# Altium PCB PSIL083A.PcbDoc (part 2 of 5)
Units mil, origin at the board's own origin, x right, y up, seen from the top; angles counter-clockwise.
Board outline 8750 x 2700 mil, 4 copper layers (Top Layer, Signal Layer 1, Signal Layer 2, Bottom Layer), stack 61.2 mil thick; 463 components, 395 nets, 2267 pads, 745 vias.
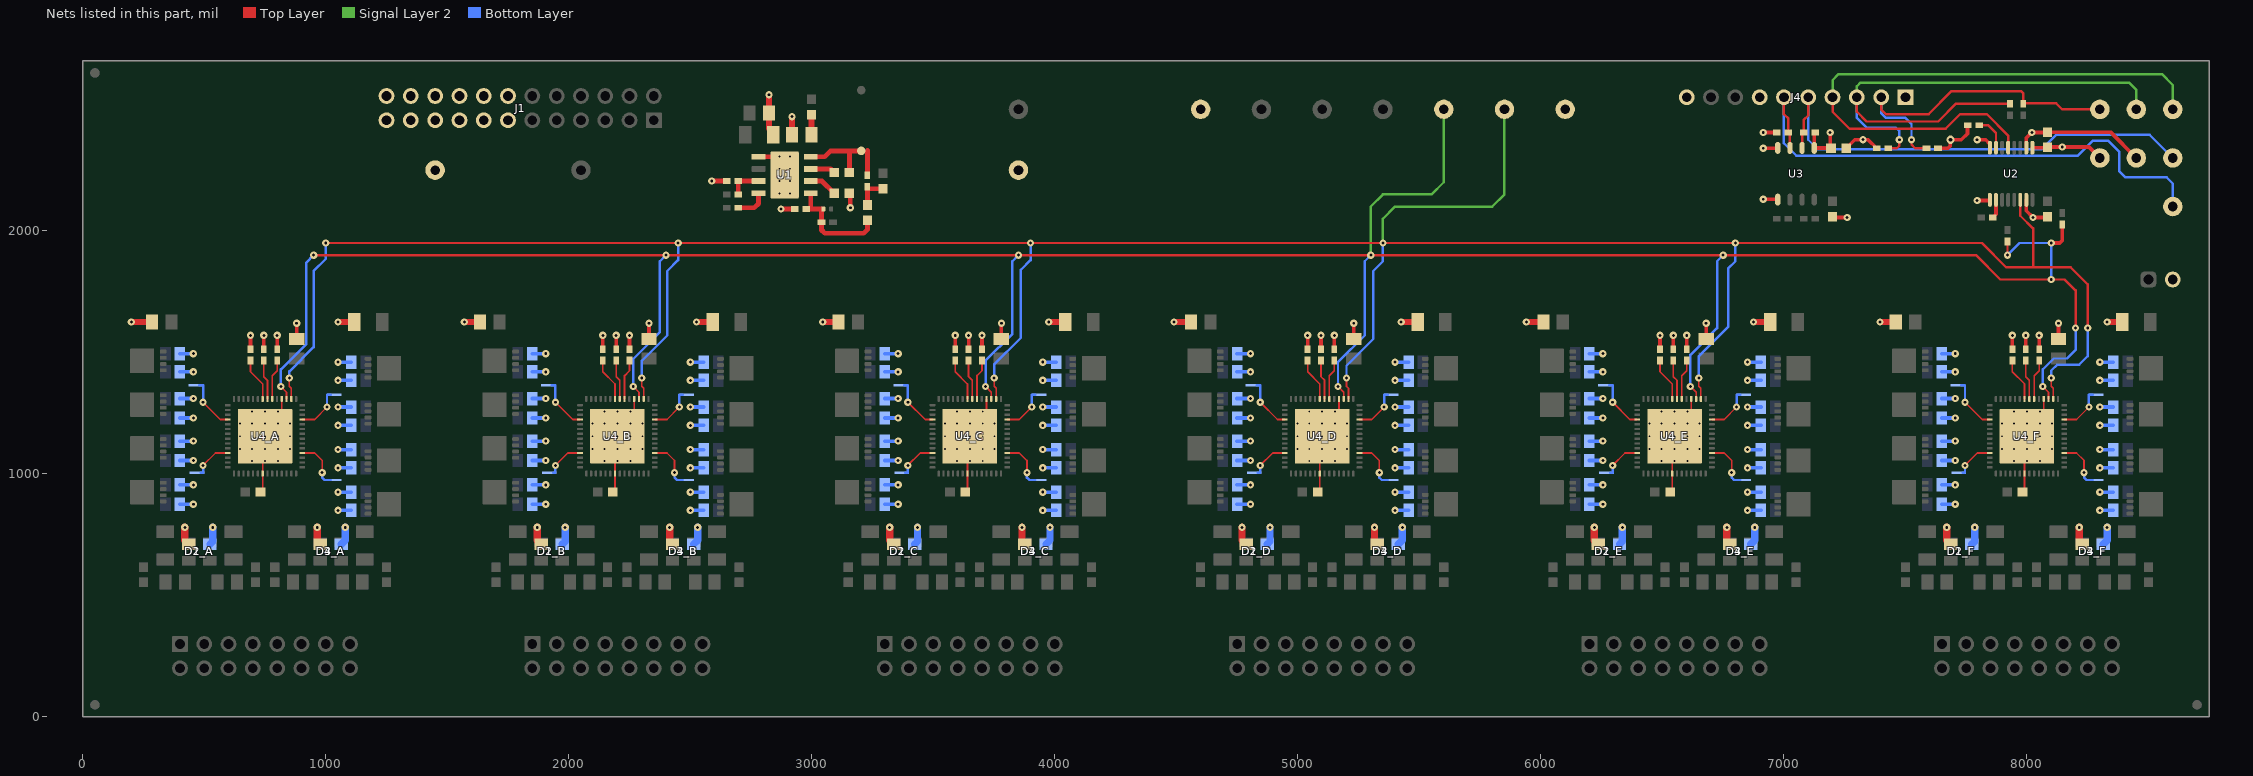
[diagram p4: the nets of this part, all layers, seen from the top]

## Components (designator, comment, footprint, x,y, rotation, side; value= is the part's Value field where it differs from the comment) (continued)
ZZ3 "These assemblies must be clean and free from flux and all contaminants. Use of no clean flux is not acceptable." AssemblyNote 175,4190 r0 top
ZZ4 "These assemblies must comply with workmanship standards IPC-A-610 Class 2, unless otherwise specified." AssemblyNote 170,4015 r0 top
ZZ5 "DO NOT TRIM CONNECTOR PINS on J5" AssemblyNote 170,3815 r0 top

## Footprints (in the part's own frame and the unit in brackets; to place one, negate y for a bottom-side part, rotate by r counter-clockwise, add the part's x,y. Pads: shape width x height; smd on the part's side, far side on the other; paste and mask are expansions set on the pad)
0402 [mm] "0402 from SM-752 data"
  rect 0.8x0.6 smd: 1(-0.6,0) 2(0.6,0)
  silkscreen extent -1.22,-0.52 1.22,0.52, body extent -0.55,-0.3 0.55,0.3, height 0.6
0603 [mm] "0603 from SM-752 data"
  rect 1x0.95 smd: 1(-0.8,0) 2(0.8,0)
  silkscreen extent -1.52,-0.69 1.52,0.69, body extent -0.87,-0.47 0.87,0.47, height 1
0805_HV [mil] "0805 with 30mil clearance between pads"
  rect 50x63 smd: 1(-40,0) 2(40,0)
  silkscreen extent -74,-40 74,40, body extent -43,-29 43,29, height 57
0805L [mm] "0805 from SM-752 data"
  rect 1.1x1.4 smd: 1(-0.75,0) 2(0.75,0)
  body extent -1.1,-0.72 1.1,0.72, height 1.45
1206 [mm] "1206 from SM-752 data"
  rect 1.3x1.85 smd: 1(-1.45,0) 2(1.45,0)
  silkscreen extent -2.4,-1.21 2.4,1.21, body extent -1.7,-0.9 1.7,0.9, height 1.35
AssemblyNote [mil] "Assembly Note"
AssemblyNoteLabel [mil] "Assembly Note for PCB Labels"
CE_Mark_5mm [mil] "Minimum text height for CE Mark"
  silkscreen extent -138,-98 138,98
D0008B_L [mm] "SOIC, 8-Leads, Body 4.9x3.9mm, Pitch 1.27mm, IPC High Density"
  oval 1.25x0.55 smd: 1(-2.7,1.905) 2(-2.7,0.635) 3(-2.7,-0.635) 4(-2.7,-1.905) 5(2.7,-1.905) 6(2.7,-0.635) 7(2.7,0.635) 8(2.7,1.905)
  silkscreen extent -3.1,-2.5 0.9,2.5, body extent -3,-2.45 3,2.45, height 1.63
DBQ0016A_N [mm] "SOP, 16-Leads, Body 4.9x3.9mm, Pitch 0.635mm, IPC Medium Density"
  oval 1.45x0.4 smd: 1(-2.725,2.222) 2(-2.725,1.587) 3(-2.725,0.952) 4(-2.725,0.317) 5(-2.725,-0.318) 6(-2.725,-0.953) 7(-2.725,-1.588) 8(-2.725,-2.223) 9(2.725,-2.222) 10(2.725,-1.587) 11(2.725,-0.952) 12(2.725,-0.317) 13(2.725,0.318) 14(2.725,0.953) 15(2.725,1.588) 16(2.725,2.223)
  silkscreen extent -3.35,-2.5 1.1,2.68, body extent -3.01,-2.45 3.01,2.45, height 1.63
DDA0008B_N [mm] "SOIC, 8-Leads, Body 4.9x3.9mm, Pitch 1.27mm, Exposed Pad, IPC Medium Density"
  rrect17% 1.45x0.6 smd: 1(-2.725,1.905) 2(-2.725,0.635) 3(-2.725,-0.635) 4(-2.725,-1.905) 5(2.725,-1.905) 6(2.725,-0.635) 7(2.725,0.635) 8(2.725,1.905)
  rrect7% 2.95x4.9 smd paste-1.5 mask-1.5: 9(0,0)
  rrect4% 2.71x3.4 on Top Paste: 9(0,0)
  rrect4% 2.71x3.4 on Top Solder: 9(0,0)
  silkscreen extent -3.5,-2.5 1.1,2.5, body extent -3.01,-2.45 3.01,2.45, height 1.57
DNH0008A_NV [mm] "8 pin VSONP, 0.65 mm pitch"
  rrect50% 0.7x0.4 smd paste-0.05 mask-0.05: 1(-1.55,0.975) 2(-1.55,0.325) 3(-1.55,-0.325) 4(-1.55,-0.975) 5(1.55,-0.975) 6(1.55,-0.325) 7(1.55,0.325) 8(1.55,0.975)
  rrect14% 0.705x1.125 on Top Paste: 9(-0.208,0.662) 9(-0.208,-0.663) 9(0.697,0.662) 9(0.697,-0.663)
  rrect6% 1.775x2.45 on Top Solder: 9(0.327,0)
  rrect4% 2.51x2.55 smd paste-1.5 mask-1.5: 9(0.645,0)
  rect 0.5x0.3 on Top Solder: 9(1.175,0.975) 9(1.175,-0.325) 9(1.175,0.325) 9(1.175,-0.975)
  silkscreen extent -1.62,-1.7 1.62,1.7, body extent -1.65,-1.65 1.65,1.66, height 0.91
FCC_disclaimer [mil]
Fiducial10-20 [mm]
  round 1 smd mask+0.5: 1(0,0)
  Top Layer keep-out circle w1.178: c0,0 r0.5
FP-GCM1555C1H121FA16D_0402-MFG [mm]
  rrect25% 0.4x0.5 smd paste+0 mask+0: 1(-0.4,0) 2(0.4,0)
  body extent -0.7,-0.38 0.7,0.38, height 0.25
Keystone5000 [mil] "For Keystone 500x miniature loop terminals"
  round 80 hole 40: 1(0,0)
  silkscreen extent -52,-52 52,52, body extent -49,-49 49,49, height 182
Keystone5001 [mil] "For Keystone 500x miniature loop terminals"
  round 80 hole 40: 1(0,0)
  silkscreen extent -52,-52 52,52, body extent -49,-49 49,49, height 182
Keystone5002 [mil] "For Keystone 500x miniature loop terminals"
  round 80 hole 40: 1(0,0)
  silkscreen extent -52,-52 52,52, body extent -49,-49 49,49, height 182
Keystone5003 [mil] "For Keystone 500x miniature loop terminals"
  round 80 hole 40: 1(0,0)
  silkscreen extent -52,-52 52,52, body extent -49,-49 49,49, height 182
Label_650x200 [mil] "Thermal Transfer Label"
  round 1 on Mech13: 0(0,0)
  silkscreen extent -325,-100 325,100, body extent -325,-100 325,100, height 1
Net-Tie_10milWide_30milLong [mil] "10mil net tie, no solder mask opening, no solder paste"
  rect 30x10 smd paste-5 mask-5: 1(-15,0) 2(15,0)
RTQ0056E [mm] "QFN, 56-Leads, Body 8x8mm, Pitch 0.5mm, Thermal Pad 5.7x5.7mm, TI Recommended"
  rrect42% 0.6x0.24 smd: 1(-3.9,3.25) 2(-3.9,2.75) 3(-3.9,2.25) 4(-3.9,1.75) 5(-3.9,1.25) 6(-3.9,0.75) 7(-3.9,0.25) 8(-3.9,-0.25) 9(-3.9,-0.75) 10(-3.9,-1.25) 11(-3.9,-1.75) 12(-3.9,-2.25) 13(-3.9,-2.75) 14(-3.9,-3.25) 29(3.9,-3.25) 30(3.9,-2.75) 31(3.9,-2.25) 32(3.9,-1.75) 33(3.9,-1.25) 34(3.9,-0.75) 35(3.9,-0.25) 36(3.9,0.25) 37(3.9,0.75) 38(3.9,1.25) 39(3.9,1.75) 40(3.9,2.25) 41(3.9,2.75) 42(3.9,3.25)
  rrect42% 0.24x0.6 smd: 15(-3.25,-3.9) 16(-2.75,-3.9) 17(-2.25,-3.9) 18(-1.75,-3.9) 19(-1.25,-3.9) 20(-0.75,-3.9) 21(-0.25,-3.9) 22(0.25,-3.9) 23(0.75,-3.9) 24(1.25,-3.9) 25(1.75,-3.9) 26(2.25,-3.9) 27(2.75,-3.9) 28(3.25,-3.9) 43(3.25,3.9) 44(2.75,3.9) 45(2.25,3.9) 46(1.75,3.9) 47(1.25,3.9) 48(0.75,3.9) 49(0.25,3.9) 50(-0.25,3.9) 51(-0.75,3.9) 52(-1.25,3.9) 53(-1.75,3.9) 54(-2.25,3.9) 55(-2.75,3.9) 56(-3.25,3.9)
  rrect9% 1.15x1.15 on Top Paste: 57(-2.025,-2.025) 57(-2.025,-0.675) 57(-2.025,0.675) 57(-2.025,2.025) 57(-0.675,-2.025) 57(-0.675,-0.675) 57(-0.675,0.675) 57(-0.675,2.025) 57(0.675,-2.025) 57(0.675,-0.675) 57(0.675,0.675) 57(0.675,2.025) 57(2.025,-2.025) 57(2.025,-0.675) 57(2.025,0.675) 57(2.025,2.025)
  rrect2% 5.7x5.7 smd paste-3: 57(0,0)
  silkscreen extent -4.22,-4.23 4.22,4.23, body extent -4,-4 4,4, height 1
SOT-143-4 [mm] "Littelfuse"
  rect 1.4x1.2 smd: 1(-1.1,0.9)
  rect 1.4x1 smd: 2(-1.1,-0.8) 3(1.1,-0.8) 4(1.1,1.1)
  silkscreen extent -1.22,1.8 -1.02,2.01, body extent -0.7,-1.37 0.7,1.67, height 1.23
SPC02SYAN [mil] "SULLINS"
  round 1 on Mech3: 0(0,0)
  body extent -98,-47 99,47, height 366
TI_Stacked_Overlay_Small [mil]
  silkscreen extent -418,-98 418,98
TSW-102-07-G-S [mm] "Samtec 100mil, 1x2, 230 mil above insulator"
  rrect50% 1.65x1.65 hole 1.016: 1(-1.27,0)
  round 1.65 hole 1.016: 2(1.27,0)
  body extent -2.54,-1.27 2.54,1.27, height 8.38
TSW-108-07-G-D [mm] "Samtec 100mil, 2x8, 230 mil above insulator"
  rrect6% 1.65x1.65 hole 1.016: 1(-8.89,-1.27)
  round 1.65 hole 1.016: 2(-8.89,1.27) 3(-6.35,-1.27) 4(-6.35,1.27) 5(-3.81,-1.27) 6(-3.81,1.27) 7(-1.27,-1.27) 8(-1.27,1.27) 9(1.27,-1.27) 10(1.27,1.27) 11(3.81,-1.27) 12(3.81,1.27) 13(6.35,-1.27) 14(6.35,1.27) 15(8.89,-1.27) 16(8.89,1.27)
  silkscreen extent -11.18,-2.54 10.16,2.54, body extent -10.16,-2.54 10.16,2.54, height 8.38
TSW-110-07-G-S [mm] "Samtec 100mil, 1x10, 230 mil above insulator"
  rrect6% 1.65x1.65 hole 1.016: 1(-11.43,0)
  round 1.65 hole 1.016: 2(-8.89,0) 3(-6.35,0) 4(-3.81,0) 5(-1.27,0) 6(1.27,0) 7(3.81,0) 8(6.35,0) 9(8.89,0) 10(11.43,0)
  silkscreen extent -12.7,-1.27 12.7,1.65, body extent -12.7,-1.27 12.7,1.27, height 8.38
TSW-112-07-G-D [mm] "Samtec 100mil, 2x12, 230 mil above insulator"
  rrect6% 1.65x1.65 hole 1.016: 1(-13.97,-1.27)
  round 1.65 hole 1.016: 2(-13.97,1.27) 3(-11.43,-1.27) 4(-11.43,1.27) 5(-8.89,-1.27) 6(-8.89,1.27) 7(-6.35,-1.27) 8(-6.35,1.27) 9(-3.81,-1.27) 10(-3.81,1.27) 11(-1.27,-1.27) 12(-1.27,1.27) 13(1.27,-1.27) 14(1.27,1.27) 15(3.81,-1.27) 16(3.81,1.27) 17(6.35,-1.27) 18(6.35,1.27) 19(8.89,-1.27) 20(8.89,1.27) 21(11.43,-1.27) 22(11.43,1.27) 23(13.97,-1.27) 24(13.97,1.27)
  silkscreen extent -16.27,-2.54 15.24,2.54, body extent -15.24,-2.54 15.24,2.54, height 8.38
WE-TPC_6823 [mm] "Wurth"
  round 0.9 smd: 1(0,3.2) 2(0,-3.15)
  Top Layer region: 3.65,-1.05 2.5,-1.05 2.485,-1.055 1.743,-2.062 0.626,-2.626 -0.626,-2.626 -1.743,-2.062 -2.485,-1.055 -2.485,-1.055 -2.5,-1.05 -3.65,-1.05 -3.65,-3.65 3.65,-3.65
  Top Layer region: -3.65,1.05 -2.5,1.05 -2.485,1.055 -1.743,2.062 -0.626,2.626 0.626,2.626 1.743,2.062 2.485,1.055 2.485,1.055 2.5,1.05 3.65,1.05 3.65,3.65 -3.65,3.65
  body extent -3.5,-3.5 3.5,3.5, height 2.5
WEEE_Minimum [mil] "WEEElie bin"
  silkscreen extent -95,-172 99,104

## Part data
C1: library part CMP-0750039-1, "CAP, CERM, 0.01 µF, 50 V,+/- 10%, X7R, 0603", Cap_Case=0603, Manufacturer="Wurth Elektronik", TempCo=X7R, Tolerance_%=10%, Value2=50V, ValueDisplayed=0.01µF
C2 C5 C25 C27 C29 C31 C33: library part CMP-0750040-1, "CAP, CERM, 1 µF, 100 V,+/- 10%, X7R, AEC-Q200 Grade 1, 1206", Cap_Case=1206, Manufacturer=MuRata, TempCo=X7R, Tolerance_%=10%, Value2=100V, ValueDisplayed=1µF
C3 C4 C15_A C15_B C15_C C15_D C15_E C15_F C16_A C16_B C16_C C16_D C16_E C16_F C17_A C17_B C17_C C17_D C17_E C17_F C18_A C18_B C18_C C18_D C18_E C18_F C19_A C19_B C19_C C19_D C19_E C19_F C20_A C20_B C20_C C20_D C20_E C20_F C21_A C21_B C21_C C21_D C21_E C21_F C22_A C22_B C22_C C22_D C22_E C22_F C26 C28 C30 C32 C34: library part CMP-0007886-2, "CAP, CERM, 0.1 uF, 100 V, +/- 10%, X7R, 0805", Cap_Case=0805, Manufacturer=TDK, Supplier Part Number 1=445-1418-1-ND, TempCo=X7R, Tolerance_%=10%, Value1="0.020726 ohm", Value2=100V, ValueDisplayed=0.1uF
C6: library part CMP-0082012-1, "CAP, CERM, 1 µF, 16 V,+/- 20%, X7R, 0603", Cap_Case=0603, Manufacturer=Samsung, Supplier Part Number 1=1276-6524-1-ND, TempCo=X7R, Tolerance_%=20%, Value2=16V, ValueDisplayed=1µF
C7: library part CMP-0007691-2, "CAP, CERM, 10 uF, 10 V, +/- 10%, X7R, 0805", Cap_Case=0805, Manufacturer="Wurth Elektronik", Supplier Part Number 1=710-885012207026, TempCo=X7R, Tolerance_%=10%, Value1=Unknown, Value2=10V, ValueDisplayed=10uF
C8: library part CMP-0007210-4, "CAP, CERM, 3300 pF, 50 V, +/- 5%, C0G/NP0, 0603", Cap_Case=0603, Manufacturer=MuRata, Supplier Part Number 1=GRM1885C1H332JA01D-ND, TempCo=C0G/NP0, Tolerance_%=5%, Value1=Unknown, Value2=50V, ValueDisplayed=3300pF
C9 C10 C11 C12 C24: library part CMP-0006837-4, "CAP, CERM, 0.1 uF, 50 V, +/- 10%, X7R, 0603", Cap_Case=0603, Manufacturer="Wurth Elektronik", TempCo=X7R, Tolerance_%=10%, Value1=Unknown, Value2=50V, ValueDisplayed=0.1uF
C13_A C13_B C13_C C13_D C13_E C13_F: library part CMP-0007099-4, "CAP, CERM, 0.1 uF, 100 V, +/- 10%, X7S, AEC-Q200 Grade 1, 0603", Cap_Case=0603, Manufacturer=TDK, Supplier Part Number 1=445-6938-1-ND, TempCo=X7S, Tolerance_%=10%, Value1="0.04959 ohm", Value2=100V, ValueDisplayed=0.1uF
C14_A C14_B C14_C C14_D C14_E C14_F: library part CMP-0007724-2, "CAP, CERM, 0.1 uF, 16 V, +/- 10%, X7R, 0805", Cap_Case=0805, Manufacturer=Kemet, Supplier Part Number 1=399-1167-1-ND, TempCo=X7R, Tolerance_%=10%, Value1="0.064 ohm", Value2=16V, ValueDisplayed=0.1uF
C23: library part CMP-0086511-1, "120pF ±1% 50V Ceramic Capacitor C0G, NP0 0402 (1005 Metric)", Manufacturer=Murata, TempCo=30ppm/°C, Tolerance_%=1%
D1_A D1_B D1_C D1_D D1_E D1_F D2_A D2_B D2_C D2_D D2_E D2_F D3_A D3_B D3_C D3_D D3_E D3_F D4_A D4_B D4_C D4_D D4_E D4_F: library part CMP-0002018-2, "ESD Suppressor Diode Arrays, 7V, SMD", Manufacturer=Bourns, Supplier Part Number 1=CD143A-SR70CT-ND
F1_A F1_B F1_C F1_D F1_E F1_F F2_A F2_B F2_C F2_D F2_E F2_F F3_A F3_B F3_C F3_D F3_E F3_F F5_A F5_B F5_C F5_D F5_E F5_F F6_A F6_B F6_C F6_D F6_E F6_F F7_A F7_B F7_C F7_D F7_E F7_F F8_A F8_B F8_C F8_D F8_E F8_F: library part CMP-0003587-2, "Fuse, 1.5 A, 63VAC/VDC, SMD", Irating_A=1.5A, Manufacturer="Bel Fuse", PartNumber="C1S 1.5", Supplier Part Number 1=507-1188-1-ND
F4_A F4_B F4_C F4_D F4_E F4_F: library part CMP-0003587-2, "Fuse, 1.5 A, 63VAC/VDC, SMD", Irating_A=1.5A, Manufacturer="Bel Fuse", Supplier Part Number 1=507-1188-1-ND
FID1 FID2 FID3 FID4 FID5 FID6: library part CMP-0077181-1, "Fiducial mark.  There is nothing to buy or mount.", Manufacturer=N/A
J1: library part CMP-0075423-1, "Header, 100mil, 12x2, Gold, TH", Color=Black, Current_A=6.3A, Manufacturer=Samtec, Supplier Part Number 1=SAM1028-12-ND, Voltage_V=550V
J2: library part CMP-0075405-2, "Header, 100mil, 2x1, Gold, TH", Color=Black, Current_A=6.3A, Manufacturer=Samtec, Supplier Part Number 1=SAM1029-02-ND, Voltage_V=550V
J4: library part CMP-0075422-1, "Header, 100mil, 10x1, Gold, TH", Color=Black, Current_A=6.3A, Manufacturer=Samtec, Supplier Part Number 1=SAM1029-10-ND, Voltage_V=550V
J5_A J5_B J5_C J5_D J5_E J5_F: library part CMP-0075418-1, "Header, 100mil, 8x2, Gold, TH", Color=Black, Current_A=6.3A, Manufacturer=Samtec, Supplier Part Number 1=SAM1028-08-ND, Voltage_V=550V
L1: library part CMP-0064704-3, "Inductor, Shielded Drum Core, Ferrite, 150 uH, 0.36 A, 0.605 ohm, SMD", Manufacturer="Wurth Elektronik", Supplier Part Number 1=732-3679-1-ND, Value1="0.605 ohm", Value2=0.36A, ValueDisplayed=150uH
L2_A L2_B L2_C L2_D L2_E L2_F L3_A L3_B L3_C L3_D L3_E L3_F L4_A L4_B L4_C L4_D L4_E L4_F L5_A L5_B L5_C L5_D L5_E L5_F L6_A L6_B L6_C L6_D L6_E L6_F L7_A L7_B L7_C L7_D L7_E L7_F L8_A L8_B L8_C L8_D L8_E L8_F L9_A L9_B L9_C L9_D L9_E L9_F: library part CMP-0078795-1, "Ferrite Bead, 600 ohm @ 100 MHz, 1 A, 0603", Manufacturer=TDK, Supplier Part Number 1=445-172898-1-ND, Value1="0.15 ohm", Value2=1A, ValueDisplayed="600 ohm"
LBL1: library part CMP-0003625-1, "Thermal Transfer Printable Labels, 0.650\" W x 0.200\" H - 10,000 per roll", Manufacturer=Brady, Supplier Part Number 1=97C5133
Logo1: library part CMP-0074838-1, "Texas Instrument Corporate Signature"
Logo2: library part CMP-0074844-1
Logo3: library part CMP-0074847-1, "FCC_disclaimer"
Logo4: library part CMP-0074769-1
NT_A1_A NT_A1_B NT_A1_C NT_A1_D NT_A1_E NT_A1_F NT_B1_A NT_B1_B NT_B1_C NT_B1_D NT_B1_E NT_B1_F NT_C1_A NT_C1_B NT_C1_C NT_C1_D NT_C1_E NT_C1_F NT_D1_A NT_D1_B NT_D1_C NT_D1_D NT_D1_E NT_D1_F: library part CMP-0078142-2, "Single point connection between nets.", Manufacturer=N/A
Q1_A Q1_B Q1_C Q1_D Q1_E Q1_F Q2_A Q2_B Q2_C Q2_D Q2_E Q2_F Q3_A Q3_B Q3_C Q3_D Q3_E Q3_F Q4_A Q4_B Q4_C Q4_D Q4_E Q4_F Q5_A Q5_B Q5_C Q5_D Q5_E Q5_F Q6_A Q6_B Q6_C Q6_D Q6_E Q6_F Q7_A Q7_B Q7_C Q7_D Q7_E Q7_F Q8_A Q8_B Q8_C Q8_D Q8_E Q8_F: library part CMP-0000969-3, "MOSFET, N-CH, 100 V, 5 A, DNH0008A (VSONP-8)", Alternate Manufacturer=None, Manufacturer="Texas Instruments", Value2="7.2 nC"
R1: library part CMP-0026021-3, "RES, 150 k, 1%, 0.063 W, AEC-Q200 Grade 0, 0402", Manufacturer=Vishay-Dale, Power_W=63mW, Supplier Part Number 1=541-150KLCT-ND, TempCo="100 ppm/C", Tolerance_%=1%, Value2=0.063W, Value_Code=150k
R2: library part CMP-0025950-3, "RES, 100 k, 1%, 0.063 W, AEC-Q200 Grade 0, 0402", Manufacturer=Vishay-Dale, Power_W=63mW, Supplier Part Number 1=541-100KLCT-ND, TempCo="100 ppm/C", Tolerance_%=1%, Value2=0.063W, Value_Code=100k
R3 R9 R10 R33 R34: library part CMP-0025958-3, "RES, 10.0 k, 1%, 0.063 W, AEC-Q200 Grade 0, 0402", Manufacturer=Vishay-Dale, Power_W=63mW, Supplier Part Number 1=541-10.0KLCT-ND, TempCo="100 ppm/C", Tolerance_%=1%, Value2=0.063W, Value_Code=10k0, ValueDisplayed=10.0k
R4: library part CMP-0025999-3, "RES, 133 k, 1%, 0.063 W, AEC-Q200 Grade 0, 0402", Manufacturer=Vishay-Dale, Power_W=63mW, Supplier Part Number 1=541-133KLCT-ND, TempCo="100 ppm/C", Tolerance_%=1%, Value2=0.063W, Value_Code=133k
R5: library part CMP-0026340-2, "RES, 3.92 k, 1%, 0.063 W, AEC-Q200 Grade 0, 0402", Manufacturer=Vishay-Dale, Power_W=63mW, Supplier Part Number 1=541-3.92KLCT-ND, TempCo="100 ppm/C", Tolerance_%=1%, Value2=0.063W, Value_Code=3k92, ValueDisplayed=3.92k
R6: library part CMP-0026512-2, "RES, 6.04 k, 1%, 0.063 W, AEC-Q200 Grade 0, 0402", Manufacturer=Vishay-Dale, Power_W=63mW, Supplier Part Number 1=541-6.04KLCT-ND, TempCo="100 ppm/C", Tolerance_%=1%, Value2=0.063W, Value_Code=6k04, ValueDisplayed=6.04k
R7: library part CMP-0025885-5, "RES, 0, 5%, 0.1 W, 0603", Manufacturer=Yageo, Power_W=100mW, Supplier Part Number 1=311-0.0GRCT-ND, TempCo="200 ppm/C", Tolerance_%=5%, Value2=0.1W, Value_Code=0000, ValueDisplayed=0
R8 R11 R12 R31 R32: library part CMP-0026938-5, "RES, 4.7 k, 5%, 0.063 W, AEC-Q200 Grade 0, 0402", Manufacturer=Vishay-Dale, Power_W=63mW, Supplier Part Number 1=541-4.7KJCT-ND, TempCo="200 ppm/C", Tolerance_%=5%, Value2=0.063W, Value_Code=4k70, ValueDisplayed=4.7k
R13_A R13_B R13_C R13_D R13_E R13_F R14_A R14_B R14_C R14_D R14_E R14_F R35_A R35_B R35_C R35_D R35_E R35_F R36 R37 R38: library part CMP-0026992-3, "RES, 0, 5%, 0.1 W, AEC-Q200 Grade 0, 0402", Manufacturer=Panasonic, Power_W=100mW, Supplier Part Number 1=P0.0JCT-ND, TempCo="600 ppm/C", Tolerance_%=5%, Value2=0.1W, Value_Code=0000, ValueDisplayed=0
R15_A R15_B R15_C R15_D R15_E R15_F R16_A R16_B R16_C R16_D R16_E R16_F R17_A R17_B R17_C R17_D R17_E R17_F R18_A R18_B R18_C R18_D R18_E R18_F R19_A R19_B R19_C R19_D R19_E R19_F R20_A R20_B R20_C R20_D R20_E R20_F R21_A R21_B R21_C R21_D R21_E R21_F R22_A R22_B R22_C R22_D R22_E R22_F R23_A R23_B R23_C R23_D R23_E R23_F R24_A R24_B R24_C R24_D R24_E R24_F R25_A R25_B R25_C R25_D R25_E R25_F R26_A R26_B R26_C R26_D R26_E R26_F R27_A R27_B R27_C R27_D R27_E R27_F R28_A R28_B R28_C R28_D R28_E R28_F R29_A R29_B R29_C R29_D R29_E R29_F R30_A R30_B R30_C R30_D R30_E R30_F: library part CMP-0021516-2, "RES, 0.51, 1%, 0.25 W, 0805", Manufacturer=Bourns, Power_W=250mW, Supplier Part Number 1=652-CRM0805FXR510ELF, TempCo="100 ppm/C", Tolerance_%=1%, Value2=0.25W, Value_Code=R510, ValueDisplayed=0.51
SH-J1: library part CMP-0003642-1, "Shunt, 100mil, Flash Gold, Black", Manufacturer="Sullins Connector Solutions", Supplier Part Number 1=S9001-ND
TP1 TP2 TP10: library part CMP-0055137-1, "Test Point, Miniature, Red, TH", Color=Red, Manufacturer=Keystone, PartNumber=5000, Supplier Part Number 1=36-5000-ND
TP3 TP4 TP14 TP15 TP18: library part CMP-0055138-1, "Test Point, Miniature, Black, TH", Color=Black, Manufacturer=Keystone, PartNumber=5001, Supplier Part Number 1=36-5001-ND
TP5 TP6 TP7 TP8 TP9: library part CMP-0055140-1, "Test Point, Miniature, Orange, TH", Color=Orange, Manufacturer=Keystone, PartNumber=5003, Supplier Part Number 1=36-5003-ND
TP11 TP12 TP13 TP16 TP17: library part CMP-0055139-1, "Test Point, Miniature, White, TH", Color=White, Manufacturer=Keystone, PartNumber=5002, Supplier Part Number 1=36-5002-ND
U1: library part CMP-0066086-2, "7.5-100V Wide Vin, 600mA Constant On-Time Synchronous Buck Regulator, DDA0008B (SOIC-8)", Alternate Manufacturer="Texas Instruments", Alternate PartNumber=LM5017MR/NOPB
U2: library part CMP-0078720-1, "High Speed, Robust EMC Triple-Channel Digital Isolators, DBQ0016A (SSOP-16)", Alternate Manufacturer="Texas Instruments", Alternate PartNumber=ISO7731FDBQR
U3: library part CMP-0076085-2, "2.5 kVrms Isolated Unidirectional Clock, Bidirectional I2C Isolators, D0008B (SOIC-8)", Alternate Manufacturer="Texas Instruments", Alternate PartNumber=ISO1541D, Operating Temperature Range="-40 to 125 C", Rating=Catalog
U4_A U4_B U4_C U4_D U4_E U4_F: library part CMP-0074661-5, "High-Power 8-Channel Power-over-Ethernet PSE with Programmable SRAM, RTQ0056E (VQFN-56)", Alternate Manufacturer="Texas Instruments", Alternate PartNumber=TPS23880RTQT
ZZ1: library part CMP-0003616-3
ZZ2: library part CMP-0077236-1
ZZ3: library part CMP-0077237-1
ZZ4 ZZ5: library part CMP-0077238-1

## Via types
v1: diameter 30, hole 12, Top Layer to Bottom Layer, 610 vias
v2: diameter 19.68, hole 7.87, Top Layer to Bottom Layer, 130 vias
v3: diameter 19.68, hole 7.87, Top Layer to Bottom Layer, tented both sides, 4 vias
v4: diameter 34, hole 16, Top Layer to Bottom Layer, 1 vias

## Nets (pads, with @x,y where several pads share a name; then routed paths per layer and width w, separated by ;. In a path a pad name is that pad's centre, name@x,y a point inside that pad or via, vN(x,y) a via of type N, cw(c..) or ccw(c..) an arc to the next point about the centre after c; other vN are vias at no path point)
3.3V_ISO: C9.1 C11.1 J4.1 R9.1 R31.2 R33.1 R34.1 TP10.1 U2.1 U3.1 | length 744
  Top Layer w15: v1(6915,2405) R34.1@6971.06,2405 ; R33.1@7128.31,2405 7124.69,2401.38 U3.1@7124.69,2341.3 C11.1@7192.2,2341.3 ; C11.1@7190,2343.5 v1(7190,2405) ; R9.1@7633.62,2340 7675,2340 7685,2350 v4(7685,2375) 7730,2375 7755,2400 7755,2433.62 R31.2@7756.38,2435 ; U2.1@8022.5,2342.28 8083.78,2342.28 C9.1@8085,2343.5 8086.5,2345 v1(8145,2345) 8255,2345 TP10.1@8300,2300
\PSE_INT_A: R8.1 R38.2 TP13.1 U4_A.45 U4_B.45 U4_C.45 U4_D.45 U4_E.45 U4_F.45 | length 12504.6
  Top Layer w7: v1(815,1360) 838.58,1336.42 U4_A.45@838.58,1308.54 ; v1(2265,1360) 2288.58,1336.42 U4_B.45@2288.58,1308.54 ; v1(3715,1360) 3738.58,1336.42 U4_C.45@3738.58,1308.54 ; v1(5165,1360) 5188.58,1336.42 U4_D.45@5188.58,1308.54 ; v1(6615,1360) 6638.58,1336.42 U4_E.45@6638.58,1308.54 ; v1(8065,1360) 8088.58,1336.42 U4_F.45@8088.58,1308.54
  Top Layer w10: v1(950,1900) v1(2400,1900) v1(3850,1900) v1(5300,1900) v1(6750,1900) 7790,1900 7890,1800 v1(8100,1800) 8155,1800 8200,1755 v1(8200,1600) ; v1(7920,1900) R38.2@7920,1956.38
  Top Layer w15: v1(8100,1950) 8135,1950 8145,1960 R8.1@8145,2026.38
  Signal Layer 2 w10: v1(5300,1900) 5300,2100 5350,2150 5550,2150 5600,2200 5600,2500.12 TP13.1@5600.23,2500.35
  Bottom Layer w10: v1(815,1360) 815,1430 920,1535 920,1870 v1(950,1900) ; v1(2265,1360) 2265,1473.54 2375,1583.54 2375,1875 v1(2400,1900) ; v1(3715,1360) 3715,1466.05 3825,1576.05 3825,1875 v1(3850,1900) ; v1(5165,1360) 5165,1460 5275,1570 5275,1875 v1(5300,1900) ; v1(6615,1360) 6615,1490 6725,1600 6725,1875 v1(6750,1900) ; v1(7920,1900) 7970,1950 v1(8100,1950) v1(8100,1800) ; v1(8065,1360) 8065,1430 8110,1475 8165,1475 8200,1510 v1(8200,1600)
\PSE_RST_A: TP11.1 U2.14 U4_A.44 U4_B.44 U4_C.44 U4_D.44 U4_E.44 U4_F.44 | length 12736.5
  Top Layer w7: v1(850,1395) 850,1360 858.27,1351.73 U4_A.44@858.27,1308.54 ; v1(2300,1395) 2300,1360 2308.27,1351.73 U4_B.44@2308.27,1308.54 ; v1(3750,1395) 3750,1360 3758.27,1351.73 U4_C.44@3758.27,1308.54 ; v1(5200,1395) 5200,1360 5208.27,1351.73 U4_D.44@5208.27,1308.54 ; v1(6650,1395) 6650,1360 6658.27,1351.73 U4_E.44@6658.27,1308.54 ; v1(8100,1395) 8100,1360 8108.27,1351.73 U4_F.44@8108.27,1308.54
  Top Layer w10: v1(1000,1950) v1(2450,1950) v1(3900,1950) v1(5350,1950) v1(6800,1950) 7815,1950 7915,1850 8025,1850 ; U2.14@7972.5,2127.72 7972.5,2062.5 8025,2010 8025,1850 ; v1(8250,1600) 8250,1780 8180,1850 8025,1850
  Signal Layer 2 w10: v1(5350,1950) 5350,2050 5400,2100 5800,2100 5850,2150 5850,2500.12 TP11.1@5850.23,2500.35
  Bottom Layer w10: v1(850,1395) 850,1421.69 950,1521.69 950,1835 1000,1885 v1(1000,1950) ; v1(2300,1395) 2300,1465 2405,1570 2405,1835 2450,1880 v1(2450,1950) ; v1(3750,1395) 3750,1450 3860,1560 3860,1840 3900,1880 v1(3900,1950) ; v1(5200,1395) 5200,1445 5310,1555 5310,1835 5350,1875 v1(5350,1950) ; v1(6650,1395) 6650,1485 6770,1605 6770,1845 6800,1875 v1(6800,1950) ; v1(8100,1395) 8100,1425 8125,1450 8215,1450 8250,1485 v1(8250,1600)
GND: C2.1 C3.1 C4.1 C5.1 C6.2 C7.2 C10.2 C12.2 C13_A.2 C13_B.2 C13_C.2 C13_D.2 C13_E.2 C13_F.2 C14_A.2 C14_B.2 C14_C.2 C14_D.2 C14_E.2 C14_F.2 C25.1 C26.1 C27.1 C28.1 C29.1 C30.1 C31.1 C32.1 C33.1 C34.1 D1_A.1 D1_B.1 D1_C.1 D1_D.1 D1_E.1 D1_F.1 D2_A.1 D2_B.1 D2_C.1 D2_D.1 D2_E.1 D2_F.1 D3_A.1 D3_B.1 D3_C.1 D3_D.1 D3_E.1 D3_F.1 D4_A.1 D4_B.1 D4_C.1 D4_D.1 D4_E.1 D4_F.1 J1.13 J1.14 J1.15 J1.16 J1.17 J1.18 J1.19 J1.20 J1.21 J1.22 J1.23 J1.24 J2.2 J4.10 NT_A1_A.2 NT_A1_B.2 NT_A1_C.2 NT_A1_D.2 NT_A1_E.2 NT_A1_F.2 NT_B1_A.2 NT_B1_B.2 NT_B1_C.2 NT_B1_D.2 NT_B1_E.2 NT_B1_F.2 NT_C1_A.2 NT_C1_B.2 NT_C1_C.2 NT_C1_D.2 NT_C1_E.2 NT_C1_F.2 NT_D1_A.2 NT_D1_B.2 NT_D1_C.2 NT_D1_D.2 NT_D1_E.2 NT_D1_F.2 R5.2 R6.2 R13_A.2 R13_B.2 R13_C.2 R13_D.2 R13_E.2 R13_F.2 R14_A.2 R14_B.2 R14_C.2 R14_D.2 R14_E.2 R14_F.2 R15_A.2 R15_B.2 R15_C.2 R15_D.2 R15_E.2 R15_F.2 R16_A.2 R16_B.2 R16_C.2 R16_D.2 R16_E.2 R16_F.2 R17_A.2 R17_B.2 R17_C.2 R17_D.2 R17_E.2 R17_F.2 R18_A.2 R18_B.2 R18_C.2 R18_D.2 R18_E.2 R18_F.2 R19_A.2 R19_B.2 R19_C.2 R19_D.2 R19_E.2 R19_F.2 R20_A.2 R20_B.2 R20_C.2 R20_D.2 R20_E.2 R20_F.2 R21_A.2 R21_B.2 R21_C.2 R21_D.2 R21_E.2 R21_F.2 R22_A.2 R22_B.2 R22_C.2 R22_D.2 R22_E.2 R22_F.2 R23_A.2 R23_B.2 R23_C.2 R23_D.2 R23_E.2 R23_F.2 R24_A.2 R24_B.2 R24_C.2 R24_D.2 R24_E.2 R24_F.2 R25_A.2 R25_B.2 R25_C.2 R25_D.2 R25_E.2 R25_F.2 R26_A.2 R26_B.2 R26_C.2 R26_D.2 R26_E.2 R26_F.2 R27_A.2 R27_B.2 R27_C.2 R27_D.2 R27_E.2 R27_F.2 R28_A.2 R28_B.2 R28_C.2 R28_D.2 R28_E.2 R28_F.2 R29_A.2 R29_B.2 R29_C.2 R29_D.2 R29_E.2 R29_F.2 R30_A.2 R30_B.2 R30_C.2 R30_D.2 R30_E.2 R30_F.2 R35_A.2 R35_B.2 R35_C.2 R35_D.2 R35_E.2 R35_F.2 TP3.1 TP4.1 TP14.1 TP18.1 U1.1 U1.9@2888.31,2230 U2.9 U2.15 U3.5 U4_A.21 U4_A.46 U4_A.57@750,1155 U4_B.21 U4_B.46 U4_B.57@2200,1155 U4_C.21 U4_C.46 U4_C.57@3650,1155 U4_D.21 U4_D.46 U4_D.57@5100,1155 U4_E.21 U4_E.46 U4_E.57@6550,1155 U4_F.21 U4_F.46 U4_F.57@8000,1155 | length 12720.5
  Top Layer w7: C13_A.2@731.5,925 740.16,933.66 U4_A.21@740.16,1001.46 740.16,1145.16 v2(750,1155) v2(803.15,1208.15) 818.9,1223.9 U4_A.46@818.9,1308.54 ; C13_B.2@2181.5,925 2190.16,933.66 U4_B.21@2190.16,1001.46 2190.16,1145.16 v2(2200,1155) v2(2253.15,1208.15) 2268.9,1223.9 U4_B.46@2268.9,1308.54 ; C13_C.2@3631.5,925 3640.16,933.66 U4_C.21@3640.16,1001.46 3640.16,1145.16 v2(3650,1155) v2(3703.15,1208.15) 3718.9,1223.9 U4_C.46@3718.9,1308.54 ; C13_D.2@5081.5,925 5090.16,933.66 U4_D.21@5090.16,1001.46 5090.16,1145.16 v2(5100,1155) v2(5153.15,1208.15) 5168.9,1223.9 U4_D.46@5168.9,1308.54 ; C13_E.2@6531.5,925 6540.16,933.66 U4_E.21@6540.16,1001.46 6540.16,1145.16 v2(6550,1155) v2(6603.15,1208.15) 6618.9,1223.9 U4_E.46@6618.9,1308.54 ; C13_F.2@7981.5,925 7990.16,933.66 U4_F.21@7990.16,1001.46 7990.16,1145.16 v2(8000,1155) v2(8053.15,1208.15) 8068.9,1223.9 U4_F.46@8068.9,1308.54
  Top Layer w15: R35_A.2@690,1513.62 v1(690,1570) ; R14_A.2@745,1513.62 v1(745,1570) ; R13_A.2@800,1513.62 v1(800,1570) ; C14_A.2@880,1555 v1(880,1620) ; R35_B.2@2140,1513.62 v1(2140,1570) ; R14_B.2@2195,1513.62 v1(2195,1570) ; R13_B.2@2250,1513.62 v1(2250,1570) ; C14_B.2@2330,1555 v1(2330,1620) ; R35_C.2@3590,1513.62 v1(3590,1570) ; R14_C.2@3645,1513.62 v1(3645,1570) ; R13_C.2@3700,1513.62 v1(3700,1570) ; C14_C.2@3780,1555 v1(3780,1620) ; R35_D.2@5040,1513.62 v1(5040,1570) ; R14_D.2@5095,1513.62 v1(5095,1570) ; R13_D.2@5150,1513.62 v1(5150,1570) ; C14_D.2@5230,1555 v1(5230,1620) ; R35_E.2@6490,1513.62 v1(6490,1570) ; R14_E.2@6545,1513.62 v1(6545,1570) ; R13_E.2@6600,1513.62 v1(6600,1570) ; C14_E.2@6680,1555 v1(6680,1620) ; v1(6915,2130) U3.5@6973.39,2130 ; C12.2@7199.69,2058.5 7203.19,2055 v1(7260,2055) ; v1(7795,2125) 7844.78,2125 U2.9@7847.5,2127.72 ; R35_F.2@7940,1513.62 v1(7940,1570) ; R14_F.2@7995,1513.62 v1(7995,1570) ; U2.15@7997.5,2127.72 7997.5,2082.5 v1(8025,2055) 8081.5,2055 C10.2@8085,2058.5 ; R13_F.2@8050,1513.62 v1(8050,1570) ; C14_F.2@8130,1555 v1(8130,1620)
  Top Layer w20: v1(2588.31,2205) R5.2@2649.68,2205 ; U1.1@2781.02,2305 2838.31,2305 2848.31,2295 2848.31,2270 U1.9@2888.31,2230 ; v1(2873.31,2090) R6.2@2929.68,2090 ; v1(3158.31,2095) C6.2@3158.31,2151.5
  Top Layer w25: v1(200,1625) C3.1@285,1625 ; v1(1050,1625) C2.1@1108.07,1625 ; v1(1570,1625) C26.1@1635,1625 ; v1(2525,1625) C25.1@2583.07,1625 ; v1(2823.31,2560) 2823.31,2421.93 C5.1@2850.24,2395 ; C7.2@2918.31,2395 v1(2918.31,2470) ; v1(3045,1625) C28.1@3110,1625 ; v1(3975,1625) C27.1@4033.07,1625 ; v1(4490,1625) C30.1@4560,1625 ; v1(5425,1625) C29.1@5483.07,1625 ; v1(5940,1625) C32.1@6010,1625 ; v1(6875,1625) C31.1@6933.07,1625 ; v1(7395,1625) C34.1@7460,1625 ; v1(8330,1625) C33.1@8383.07,1625
  Top Layer w30: v1(420,780) 420,727.13 D2_A.1@436.69,710.43 ; v1(965,780) 965,722.13 D4_A.1@976.69,710.43 ; v1(1870,780) 1870,727.13 D2_B.1@1886.69,710.43 ; v1(2415,780) 2415,722.13 D4_B.1@2426.69,710.43 ; v1(3320,780) 3320,727.13 D2_C.1@3336.69,710.43 ; v1(3865,780) 3865,722.13 D4_C.1@3876.69,710.43 ; v1(4770,780) 4770,727.13 D2_D.1@4786.69,710.43 ; v1(5315,780) 5315,722.13 D4_D.1@5326.69,710.43 ; v1(6220,780) 6220,727.13 D2_E.1@6236.69,710.43 ; v1(6765,780) 6765,722.13 D4_E.1@6776.69,710.43 ; v1(7670,780) 7670,727.13 D2_F.1@7686.69,710.43 ; v1(8215,780) 8215,722.13 D4_F.1@8226.69,710.43
  Bottom Layer w15: R26_A.2@399.53,875 v1(455,875) ; R25_A.2@399.53,955 v1(455,955) ; R24_A.2@399.53,1055 v1(455,1055) ; R23_A.2@399.53,1135 v1(455,1135) ; R18_A.2@399.53,1230 v1(455,1230) ; R17_A.2@399.53,1310 v1(455,1310) ; R16_A.2@399.53,1420 v1(455,1420) ; R15_A.2@399.53,1495 v1(455,1495) ; v1(1050,850) R19_A.2@1105.47,850 ; v1(1050,925) R20_A.2@1105.47,925 ; v1(1050,1025) R21_A.2@1105.47,1025 ; v1(1050,1100) R22_A.2@1105.47,1100 ; v1(1050,1200) R27_A.2@1105.47,1200 ; v1(1050,1275) R28_A.2@1105.47,1275 ; v1(1050,1385) R29_A.2@1105.47,1385 ; v1(1050,1460) R30_A.2@1105.47,1460 ; R26_B.2@1849.53,875 v1(1905,875) ; R25_B.2@1849.53,955 v1(1905,955) ; R24_B.2@1849.53,1055 v1(1905,1055) ; R23_B.2@1849.53,1135 v1(1905,1135) ; R18_B.2@1849.53,1230 v1(1905,1230) ; R17_B.2@1849.53,1310 v1(1905,1310) ; R16_B.2@1849.53,1420 v1(1905,1420) ; R15_B.2@1849.53,1495 v1(1905,1495) ; v1(2500,850) R19_B.2@2555.47,850 ; v1(2500,925) R20_B.2@2555.47,925 ; v1(2500,1025) R21_B.2@2555.47,1025 ; v1(2500,1100) R22_B.2@2555.47,1100 ; v1(2500,1200) R27_B.2@2555.47,1200 ; v1(2500,1275) R28_B.2@2555.47,1275 ; v1(2500,1385) R29_B.2@2555.47,1385 ; v1(2500,1460) R30_B.2@2555.47,1460 ; R26_C.2@3299.53,875 v1(3355,875) ; R25_C.2@3299.53,955 v1(3355,955) ; R24_C.2@3299.53,1055 v1(3355,1055) ; R23_C.2@3299.53,1135 v1(3355,1135) ; R18_C.2@3299.53,1230 v1(3355,1230) ; R17_C.2@3299.53,1310 v1(3355,1310) ; R16_C.2@3299.53,1420 v1(3355,1420) ; R15_C.2@3299.53,1495 v1(3355,1495) ; v1(3950,850) R19_C.2@4005.47,850 ; v1(3950,925) R20_C.2@4005.47,925 ; v1(3950,1025) R21_C.2@4005.47,1025 ; v1(3950,1100) R22_C.2@4005.47,1100 ; v1(3950,1200) R27_C.2@4005.47,1200 ; v1(3950,1275) R28_C.2@4005.47,1275 ; v1(3950,1385) R29_C.2@4005.47,1385 ; v1(3950,1460) R30_C.2@4005.47,1460 ; R26_D.2@4749.53,875 v1(4805,875) ; R25_D.2@4749.53,955 v1(4805,955) ; R24_D.2@4749.53,1055 v1(4805,1055) ; R23_D.2@4749.53,1135 v1(4805,1135) ; R18_D.2@4749.53,1230 v1(4805,1230) ; R17_D.2@4749.53,1310 v1(4805,1310) ; R16_D.2@4749.53,1420 v1(4805,1420) ; R15_D.2@4749.53,1495 v1(4805,1495) ; v1(5400,850) R19_D.2@5455.47,850 ; v1(5400,925) R20_D.2@5455.47,925 ; v1(5400,1025) R21_D.2@5455.47,1025 ; v1(5400,1100) R22_D.2@5455.47,1100 ; v1(5400,1200) R27_D.2@5455.47,1200 ; v1(5400,1275) R28_D.2@5455.47,1275 ; v1(5400,1385) R29_D.2@5455.47,1385 ; v1(5400,1460) R30_D.2@5455.47,1460 ; R26_E.2@6199.53,875 v1(6255,875) ; R25_E.2@6199.53,955 v1(6255,955) ; R24_E.2@6199.53,1055 v1(6255,1055) ; R23_E.2@6199.53,1135 v1(6255,1135) ; R18_E.2@6199.53,1230 v1(6255,1230) ; R17_E.2@6199.53,1310 v1(6255,1310) ; R16_E.2@6199.53,1420 v1(6255,1420) ; R15_E.2@6199.53,1495 v1(6255,1495) ; v1(6850,850) R19_E.2@6905.47,850 ; v1(6850,925) R20_E.2@6905.47,925 ; v1(6850,1025) R21_E.2@6905.47,1025 ; v1(6850,1100) R22_E.2@6905.47,1100 ; v1(6850,1200) R27_E.2@6905.47,1200 ; v1(6850,1275) R28_E.2@6905.47,1275 ; v1(6850,1385) R29_E.2@6905.47,1385 ; v1(6850,1460) R30_E.2@6905.47,1460 ; R26_F.2@7649.53,875 v1(7705,875) ; R25_F.2@7649.53,955 v1(7705,955) ; R24_F.2@7649.53,1055 v1(7705,1055) ; R23_F.2@7649.53,1135 v1(7705,1135) ; R18_F.2@7649.53,1230 v1(7705,1230) ; R17_F.2@7649.53,1310 v1(7705,1310) ; R16_F.2@7649.53,1420 v1(7705,1420) ; R15_F.2@7649.53,1495 v1(7705,1495) ; v1(8300,850) R19_F.2@8355.47,850 ; v1(8300,925) R20_F.2@8355.47,925 ; v1(8300,1025) R21_F.2@8355.47,1025 ; v1(8300,1100) R22_F.2@8355.47,1100 ; v1(8300,1200) R27_F.2@8355.47,1200 ; v1(8300,1275) R28_F.2@8355.47,1275 ; v1(8300,1385) R29_F.2@8355.47,1385 ; v1(8300,1460) R30_F.2@8355.47,1460
  Bottom Layer w30: D1_A.1@523.31,710.43 535,722.13 v1(535,780) ; D3_A.1@1063.31,710.43 1080,727.13 v1(1080,780) ; D1_B.1@1973.31,710.43 1985,722.13 v1(1985,780) ; D3_B.1@2513.31,710.43 2530,727.13 v1(2530,780) ; D1_C.1@3423.31,710.43 3435,722.13 v1(3435,780) ; D3_C.1@3963.31,710.43 3980,727.13 v1(3980,780) ; D1_D.1@4873.31,710.43 4885,722.13 v1(4885,780) ; D3_D.1@5413.31,710.43 5430,727.13 v1(5430,780) ; D1_E.1@6323.31,710.43 6335,722.13 v1(6335,780) ; D3_E.1@6863.31,710.43 6880,727.13 v1(6880,780) ; D1_F.1@7773.31,710.43 7785,722.13 v1(7785,780) ; D3_F.1@8313.31,710.43 8330,727.13 v1(8330,780)
  other v2: 696.85,1052.64 750,1052.64 803.15,1052.64 2146.85,1052.64 2200,1052.64 2253.15,1052.64 3596.85,1052.64 3650,1052.64 3703.15,1052.64 5046.85,1052.64 5100,1052.64 5153.15,1052.64 6496.85,1052.64 6550,1052.64 6603.15,1052.64 7946.85,1052.64 8000,1052.64 8053.15,1052.64 647.64,1101.85 696.85,1101.85 750,1101.85 803.15,1101.85 852.36,1101.85 2097.64,1101.85 2146.85,1101.85 2200,1101.85 2253.15,1101.85 2302.36,1101.85 3547.64,1101.85 3596.85,1101.85 3650,1101.85 3703.15,1101.85 3752.36,1101.85 4997.64,1101.85 5046.85,1101.85 5100,1101.85 5153.15,1101.85 5202.36,1101.85 6447.64,1101.85 6496.85,1101.85 6550,1101.85 6603.15,1101.85 6652.36,1101.85 7897.64,1101.85 7946.85,1101.85 8000,1101.85 8053.15,1101.85 8102.36,1101.85 647.64,1155 696.85,1155 803.15,1155 852.36,1155 2097.64,1155 2146.85,1155 2253.15,1155 2302.36,1155 3547.64,1155 3596.85,1155 3703.15,1155 3752.36,1155 4997.64,1155 5046.85,1155 5153.15,1155 5202.36,1155 6447.64,1155 6496.85,1155 6603.15,1155 6652.36,1155 7897.64,1155 7946.85,1155 8053.15,1155 8102.36,1155 647.64,1208.15 696.85,1208.15 750,1208.15 852.36,1208.15 2097.64,1208.15 2146.85,1208.15 2200,1208.15 2302.36,1208.15 3547.64,1208.15 3596.85,1208.15 3650,1208.15 3752.36,1208.15 4997.64,1208.15 5046.85,1208.15 5100,1208.15 5202.36,1208.15 6447.64,1208.15 6496.85,1208.15 6550,1208.15 6652.36,1208.15 7897.64,1208.15 7946.85,1208.15 8000,1208.15 8102.36,1208.15 696.85,1257.36 750,1257.36 803.15,1257.36 2146.85,1257.36 2200,1257.36 2253.15,1257.36 3596.85,1257.36 3650,1257.36 3703.15,1257.36 5046.85,1257.36 5100,1257.36 5153.15,1257.36 6496.85,1257.36 6550,1257.36 6603.15,1257.36 7946.85,1257.36 8000,1257.36 8053.15,1257.36 2866.65,2204.41 2909.96,2204.41 2866.65,2255.59 2909.96,2255.59
  other v3: 2866.65,2153.23 2909.96,2153.23 2866.65,2306.77 2909.96,2306.77
GND_ISO: C9.2 C11.2 J4.7 R10.2 TP15.1 U2.2 U2.8 U3.4 | length 832.3
  Top Layer w15: v1(6915,2340) U3.4@6973.39,2340 ; C11.2@7256.5,2340 7291.8,2375.3 v1(7325,2375.3) 7346.08,2375.3 R10.2@7381.38,2340 ; v1(7795,2375) 7830.3,2375 7847.5,2357.8 U2.8@7847.5,2342.28 ; U2.2@7997.5,2342.28 7997.5,2382.5 v1(8020,2405) C9.2@8083.5,2405 ; C9.2@8085,2406.5 8343.5,2406.5 TP15.1@8450,2300
NetC1_1: C1.1 L1.1 R4.1 U1.8 | length 455
  Top Layer w20: U1.8@2995.59,2305 3053.31,2305 3077.32,2329.02 L1.1@3203.31,2329.02 ; C1.1@3154.8,2240 3154.8,2327.52 L1.1@3201.81,2327.52 ; 3227.32,2329.02 3228.31,2330 R4.1@3228.31,2228.62
NetC1_2: C1.2 U1.7 | length 102.4
  Top Layer w20: U1.7@2995.59,2255 3076.81,2255 C1.2@3091.81,2240
NetC6_1: C6.1 U1.6 | length 116.9
  Top Layer w20: U1.6@2995.59,2205 3041.81,2205 C6.1@3091.81,2155
NetC7_1: C7.1 R7.2 | length 83.5
  Top Layer w25: C7.1@2998.31,2395 R7.2@2998.31,2478.5
NetC8_2: C8.2 C24.1 R4.2 | length 132
  Top Layer w20: C24.1@3228.31,2106.5 R4.2@3228.31,2181.38 ; R4.2@3236.18,2173.5 C8.2@3293.31,2173.5
NetC23_2: C23.2 C24.2 R3.2 R6.1 U1.5 | length 450.8
  Top Layer w20: R6.1@2976.93,2090 3039.68,2090 R3.2@3039.68,2035 3039.68,2003.62 3053.31,1990 3213.31,1990 3228.31,2005 C24.2@3228.31,2043.5 ; 2995.59,2092.28 U1.5@2995.59,2155
NetJ4_2: J4.2 R9.2 R36.1 TP5.1 | length 1415.3
  Top Layer w10: J4.2@7400,2550 7400,2500 7420,2480 7595,2480 7690,2575 7975,2575 7985,2565 R36.1@7985,2523.62 7986.38,2525 8120,2525 8145,2500 TP5.1@8300,2500 ; v1(7525,2375) 7525,2355 7540,2340 R9.2@7586.38,2340
  Bottom Layer w10: J4.2@7400,2550 7400,2485 7420,2465 7500,2465 7525,2440 v1(7525,2375)
NetJ4_3: J4.3 R10.1 R37.1 TP6.1 | length 2424.2
  Top Layer w10: J4.3@7300,2550 7300,2490 7340,2450 7635,2450 7708.62,2523.62 R37.1@7930,2523.62 ; R10.1@7428.62,2340 7465,2340 7475,2350 v1(7475,2375)
  Signal Layer 2 w10: J4.3@7300,2550 7300,2595 7315,2610 8420,2610 8450,2580 TP6.1@8450,2500
  Bottom Layer w10: J4.3@7300,2550 7300,2465 7340,2425 7460.3,2425 7475,2410.3 v1(7475,2375)
NetJ4_4: J4.4 TP7.1 U2.5 | length 2521.8
  Top Layer w10: J4.4@7200,2550 7200,2490 7270,2420 7665,2420 7725,2480 7835,2480 7922.5,2392.5 U2.5@7922.5,2342.28
  Signal Layer 2 w10: J4.4@7200,2550 7200,2620 7225,2645 8555,2645 8600,2600 TP7.1@8600,2500
NetJ4_5: J4.5 R33.2 TP9.1 U3.2 | length 1975
  Top Layer w10: U3.2@7074.69,2341.3 7074.69,2398.62 R33.2@7081.06,2405 7081.06,2456.06 7100,2475 J4.5@7100,2550
  Bottom Layer w10: J4.5@7100,2550 7100,2375 7140,2335 8060,2335 8120,2395 8505,2395 TP9.1@8600,2300
NetJ4_6: J4.6 R34.2 TP8.1 U3.3 | length 2253.4
  Top Layer w10: J4.6@7000,2550 7000,2480 7018.31,2461.69 7018.31,2420 ; R34.2@7018.31,2405 7024.69,2398.62 U3.3@7024.69,2341.3
  Bottom Layer w10: J4.6@7000,2550 7000,2360.68 7050.68,2310 8210,2310 8270,2370 8335,2370 8380,2325 8380,2245 8405,2220 8575,2220 8600,2195 TP8.1@8600,2100
NetNT_A1_A_1: NT_A1_A.1 U4_A.4 | length 215.9
  Top Layer w7: v1(495,1295) 566.1,1223.9 U4_A.4@596.46,1223.9
  Bottom Layer w10: NT_A1_A.1@480,1365 495,1365 v1(495,1295)
NetNT_A1_B_1: NT_A1_B.1 U4_B.4 | length 215.9
  Top Layer w7: v1(1945,1295) 2016.1,1223.9 U4_B.4@2046.46,1223.9
  Bottom Layer w10: NT_A1_B.1@1930,1365 1945,1365 v1(1945,1295)
NetNT_A1_C_1: NT_A1_C.1 U4_C.4 | length 215.9
  Top Layer w7: v1(3395,1295) 3466.1,1223.9 U4_C.4@3496.46,1223.9
  Bottom Layer w10: NT_A1_C.1@3380,1365 3395,1365 v1(3395,1295)
NetNT_A1_D_1: NT_A1_D.1 U4_D.4 | length 215.9
  Top Layer w7: v1(4845,1295) 4916.1,1223.9 U4_D.4@4946.46,1223.9
  Bottom Layer w10: NT_A1_D.1@4830,1365 4845,1365 v1(4845,1295)
NetNT_A1_E_1: NT_A1_E.1 U4_E.4 | length 215.9
  Top Layer w7: v1(6295,1295) 6366.1,1223.9 U4_E.4@6396.46,1223.9
  Bottom Layer w10: NT_A1_E.1@6280,1365 6295,1365 v1(6295,1295)
NetNT_A1_F_1: NT_A1_F.1 U4_F.4 | length 215.9
  Top Layer w7: v1(7745,1295) 7816.1,1223.9 U4_F.4@7846.46,1223.9
  Bottom Layer w10: NT_A1_F.1@7730,1365 7745,1365 v1(7745,1295)
NetNT_B1_A_1: NT_B1_A.1 U4_A.11 | length 162.6
  Top Layer w7: v1(495,1035) 546.1,1086.1 U4_A.11@596.46,1086.1
  Bottom Layer w10: NT_B1_A.1@485,1005 495,1005 v1(495,1035)
NetNT_B1_B_1: NT_B1_B.1 U4_B.11 | length 162.6
  Top Layer w7: v1(1945,1035) 1996.1,1086.1 U4_B.11@2046.46,1086.1
  Bottom Layer w10: NT_B1_B.1@1935,1005 1945,1005 v1(1945,1035)
NetNT_B1_C_1: NT_B1_C.1 U4_C.11 | length 162.6
  Top Layer w7: v1(3395,1035) 3446.1,1086.1 U4_C.11@3496.46,1086.1
  Bottom Layer w10: NT_B1_C.1@3385,1005 3395,1005 v1(3395,1035)
NetNT_B1_D_1: NT_B1_D.1 U4_D.11 | length 162.6
  Top Layer w7: v1(4845,1035) 4896.1,1086.1 U4_D.11@4946.46,1086.1
  Bottom Layer w10: NT_B1_D.1@4835,1005 4845,1005 v1(4845,1035)
NetNT_B1_E_1: NT_B1_E.1 U4_E.11 | length 162.6
  Top Layer w7: v1(6295,1035) 6346.1,1086.1 U4_E.11@6396.46,1086.1
  Bottom Layer w10: NT_B1_E.1@6285,1005 6295,1005 v1(6295,1035)
NetNT_B1_F_1: NT_B1_F.1 U4_F.11 | length 162.6
  Top Layer w7: v1(7745,1035) 7796.1,1086.1 U4_F.11@7846.46,1086.1
  Bottom Layer w10: NT_B1_F.1@7735,1005 7745,1005 v1(7745,1035)
NetNT_C1_A_1: NT_C1_A.1 U4_A.32 | length 203.5
  Top Layer w7: U4_A.32@903.54,1086.1 953.9,1086.1 985,1055 v1(985,1005)
  Bottom Layer w10: v1(985,1005) 985,985 995,975 NT_C1_A.1@1020,975
NetNT_C1_B_1: NT_C1_B.1 U4_B.32 | length 203.5
  Top Layer w7: U4_B.32@2353.54,1086.1 2403.9,1086.1 2435,1055 v1(2435,1005)
  Bottom Layer w10: v1(2435,1005) 2435,985 2445,975 NT_C1_B.1@2470,975
NetNT_C1_C_1: NT_C1_C.1 U4_C.32 | length 203.5
  Top Layer w7: U4_C.32@3803.54,1086.1 3853.9,1086.1 3885,1055 v1(3885,1005)
  Bottom Layer w10: v1(3885,1005) 3885,985 3895,975 NT_C1_C.1@3920,975
NetNT_C1_D_1: NT_C1_D.1 U4_D.32 | length 203.5
  Top Layer w7: U4_D.32@5253.54,1086.1 5303.9,1086.1 5335,1055 v1(5335,1005)
  Bottom Layer w10: v1(5335,1005) 5335,985 5345,975 NT_C1_D.1@5370,975
NetNT_C1_E_1: NT_C1_E.1 U4_E.32 | length 203.5
  Top Layer w7: U4_E.32@6703.54,1086.1 6753.9,1086.1 6785,1055 v1(6785,1005)
  Bottom Layer w10: v1(6785,1005) 6785,985 6795,975 NT_C1_E.1@6820,975
NetNT_C1_F_1: NT_C1_F.1 U4_F.32 | length 203.5
  Top Layer w7: U4_F.32@8153.54,1086.1 8203.9,1086.1 8235,1055 v1(8235,1005)
  Bottom Layer w10: v1(8235,1005) 8235,985 8245,975 NT_C1_F.1@8270,975
NetNT_D1_A_1: NT_D1_A.1 U4_A.39 | length 187.6
  Top Layer w7: U4_A.39@903.54,1223.9 953.9,1223.9 v1(1005,1275)
  Bottom Layer w10: v1(1005,1275) 1005,1325 NT_D1_A.1@1020,1325
NetNT_D1_B_1: NT_D1_B.1 U4_B.39 | length 187.6
  Top Layer w7: U4_B.39@2353.54,1223.9 2403.9,1223.9 v1(2455,1275)
  Bottom Layer w10: v1(2455,1275) 2455,1325 NT_D1_B.1@2470,1325
NetNT_D1_C_1: NT_D1_C.1 U4_C.39 | length 187.6
  Top Layer w7: U4_C.39@3803.54,1223.9 3853.9,1223.9 v1(3905,1275)
  Bottom Layer w10: v1(3905,1275) 3905,1325 NT_D1_C.1@3920,1325
NetNT_D1_D_1: NT_D1_D.1 U4_D.39 | length 187.6
  Top Layer w7: U4_D.39@5253.54,1223.9 5303.9,1223.9 v1(5355,1275)
  Bottom Layer w10: v1(5355,1275) 5355,1325 NT_D1_D.1@5370,1325
NetNT_D1_E_1: NT_D1_E.1 U4_E.39 | length 187.6
  Top Layer w7: U4_E.39@6703.54,1223.9 6753.9,1223.9 v1(6805,1275)
  Bottom Layer w10: v1(6805,1275) 6805,1325 NT_D1_E.1@6820,1325
NetNT_D1_F_1: NT_D1_F.1 U4_F.39 | length 187.6
  Top Layer w7: U4_F.39@8153.54,1223.9 8203.9,1223.9 v1(8255,1275)
  Bottom Layer w10: v1(8255,1275) 8255,1325 NT_D1_F.1@8270,1325
NetR1_2: R1.2 U1.4 | length 133.7
  Top Layer w20: R1.2@2696.93,2095 2763.31,2095 2781.02,2112.72 U1.4@2781.02,2155
NetR2_2: R2.2 R5.1 U1.3 | length 139.1
  Top Layer w20: R2.2@2696.93,2150 R5.1@2696.93,2205 U1.3@2781.02,2205
NetR13_A_1: R13_A.1 U4_A.48 | length 166.3
  Top Layer w7: U4_A.48@779.53,1308.54 779.53,1404.53 800,1425 R13_A.1@800,1466.38
NetR13_B_1: R13_B.1 U4_B.48 | length 166.3
  Top Layer w7: U4_B.48@2229.53,1308.54 2229.53,1404.53 2250,1425 R13_B.1@2250,1466.38
NetR13_C_1: R13_C.1 U4_C.48 | length 166.3
  Top Layer w7: U4_C.48@3679.53,1308.54 3679.53,1404.53 3700,1425 R13_C.1@3700,1466.38
NetR13_D_1: R13_D.1 U4_D.48 | length 166.3
  Top Layer w7: U4_D.48@5129.53,1308.54 5129.53,1404.53 5150,1425 R13_D.1@5150,1466.38
NetR13_E_1: R13_E.1 U4_E.48 | length 166.3
  Top Layer w7: U4_E.48@6579.53,1308.54 6579.53,1404.53 6600,1425 R13_E.1@6600,1466.38
NetR13_F_1: R13_F.1 U4_F.48 | length 166.3
  Top Layer w7: U4_F.48@8029.53,1308.54 8029.53,1404.53 8050,1425 R13_F.1@8050,1466.38
NetR14_A_1: R14_A.1 U4_A.49 | length 164
  Top Layer w7: R14_A.1@745,1466.38 745,1400 759.84,1385.16 U4_A.49@759.84,1308.54
NetR14_B_1: R14_B.1 U4_B.49 | length 164
  Top Layer w7: R14_B.1@2195,1466.38 2195,1400 2209.84,1385.16 U4_B.49@2209.84,1308.54
NetR14_C_1: R14_C.1 U4_C.49 | length 164
  Top Layer w7: R14_C.1@3645,1466.38 3645,1400 3659.84,1385.16 U4_C.49@3659.84,1308.54
NetR14_D_1: R14_D.1 U4_D.49 | length 164
  Top Layer w7: R14_D.1@5095,1466.38 5095,1400 5109.84,1385.16 U4_D.49@5109.84,1308.54
NetR14_E_1: R14_E.1 U4_E.49 | length 164
  Top Layer w7: R14_E.1@6545,1466.38 6545,1400 6559.84,1385.16 U4_E.49@6559.84,1308.54
NetR14_F_1: R14_F.1 U4_F.49 | length 164
  Top Layer w7: R14_F.1@7995,1466.38 7995,1400 8009.84,1385.16 U4_F.49@8009.84,1308.54
NetR31_1: R31.1 U2.7 | length 142.6
  Top Layer w10: R31.1@7803.62,2435 7840,2435 7872.5,2402.5 U2.7@7872.5,2342.28
NetR32_2: R32.2 U2.10 | length 78.5
  Top Layer w15: R32.2@7858.62,2055 7872.5,2068.88 U2.10@7872.5,2127.72
NetR35_A_1: R35_A.1 U4_A.50 | length 178.6
  Top Layer w7: R35_A.1@690,1466.38 690,1420 740.16,1369.84 U4_A.50@740.16,1308.54
NetR35_B_1: R35_B.1 U4_B.50 | length 178.6
  Top Layer w7: R35_B.1@2140,1466.38 2140,1420 2190.16,1369.84 U4_B.50@2190.16,1308.54
NetR35_C_1: R35_C.1 U4_C.50 | length 178.6
  Top Layer w7: R35_C.1@3590,1466.38 3590,1420 3640.16,1369.84 U4_C.50@3640.16,1308.54
NetR35_D_1: R35_D.1 U4_D.50 | length 178.6
  Top Layer w7: R35_D.1@5040,1466.38 5040,1420 5090.16,1369.84 U4_D.50@5090.16,1308.54
NetR35_E_1: R35_E.1 U4_E.50 | length 178.6
  Top Layer w7: R35_E.1@6490,1466.38 6490,1420 6540.16,1369.84 U4_E.50@6540.16,1308.54
NetR35_F_1: R35_F.1 U4_F.50 | length 178.6
  Top Layer w7: R35_F.1@7940,1466.38 7940,1420 7990.16,1369.84 U4_F.50@7990.16,1308.54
